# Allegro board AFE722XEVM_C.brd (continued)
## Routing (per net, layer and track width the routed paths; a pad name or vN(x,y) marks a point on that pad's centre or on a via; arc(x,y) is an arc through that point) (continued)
5V:
  vias: v1(123.83,103.12) v1(123.83,102.49) v1(123.83,101.85) v1(123.83,101.22) v1(123.83,100.58) v1(124.46,103.12) v1(124.46,102.49) v1(124.46,101.85) v1(124.46,101.22) v1(124.46,100.58) v1(124.46,99.95)
+1.8V_CLK: length 6.2
  TOP w0.254: U1.10 48.88,43.98 v1(49.45,44.55) 49.48,44.55 v1(49.91,44.98) ; C2.1 50.69,46.04 v1(50.42,45.77)
  BOTTOM w0.508: C4.1 49.25,44.2 49.25,44.3 49.91,44.96 v1(49.91,44.98) 50.42,45.49 v1(50.42,45.77) ; v1(50.06,48.44) 50.73,47.77 C3.1 v1(49.99,47.02)
  vias: v1(47.6,15.49) v1(47.6,14.86) v1(47.6,14.22) v1(48.23,15.49) v1(48.23,14.86) v1(48.23,14.22) v1(48.87,15.49) v1(48.87,14.86) v1(48.87,14.22)
+1.8VA_ADC: length 30.3
  TOP w0.254: C25.1 v1(53.29,43.03) ; 52.4,41.17 52.06,40.84 U1.1
  TOP w0.305: v1(54.1,39.95) 54.13,39.98 54.13,40.87 v1(53.87,41.12) 53.75,41 53.06,41 v1(52.96,40.89) 52.68,40.89 52.4,41.17 v1(52.73,41.5) ; v1(53.29,43.03) 52.96,43.03 v1(52.73,42.8) 52.5,43.03 v1(51.99,43.03) 51.64,42.67 v1(51.64,42.49) 51,41.86 51,41.85 ; v1(53.21,39.4) 53.21,38.96 v1(53.04,38.79) v1(52.6,39.22) 52.09,39.73 U1.64 ; v1(52.55,37.82) 52.55,37.87 v1(52.1,38.33) 51.4,39.02 U1.62 ; C23.1 v1(52.12,44.65) 51.64,44.65 v1(51.41,44.42) 51.41,44.17 51.13,43.89 v1(51.1,43.89) 50.9,43.89 v1(50.52,43.51) 49.94,42.93 U1.7
  BOTTOM w0.508: 52.31,39.89 52.31,39.69 52.6,39.4 v1(53.21,39.4) ; 52.26,41.03 v1(52.73,41.5) ; 52.26,41.03 C26.1 ; 52.26,41.03 52.82,41.03 v1(52.96,40.89) ; 54.76,40.61 54.36,40.61 v1(53.87,41.12) ; 54.76,40.61 C35.1 ; 54.76,40.61 v1(54.1,39.95) ; v1(53.04,38.79) 52.58,38.79 52.06,39.31 C28.1 ; v1(53.29,43.03) 52.96,43.03 v1(52.73,42.8) C32.1 ; 51.3,38.72 51.7,38.72 v1(52.1,38.33) 52.1,38.28 v1(52.55,37.82) ; v1(52.12,44.65) 51.64,44.65 v1(51.41,44.42) 51.41,44.17 50.8,43.56 50.14,43.56 C29.1 ; C31.1 50.52,42.82 v1(50.52,43.51) ; 50.96,42.15 51.3,42.15 v1(51.64,42.49) 51.99,42.85 v1(51.99,43.03)
  vias: v1(47.6,19.43) v1(47.6,18.8) v1(47.6,18.16) v1(48.23,19.43) v1(48.23,18.8) v1(48.23,18.16) v1(48.87,19.43) v1(48.87,18.8) v1(48.87,18.16)
+1.8VD: length 25
  TOP w0.254: v1(47.88,33.45) 47.88,33.55 47.4,34.03 47.19,34.03 46.8,34.43 U1.49 ; C8.1 38.37,42.15 v1(38.66,41.86) 38.63,41.83 v1(38.63,41.12) ; C10.1 41.47,35.04 41.68,35.26 v1(41.68,35.38) 41.74,35.38 42.24,35.88 42.24,35.91 v1(42.6,36.27) 43.22,36.9 U1.41 ; v1(39.78,41.4) 40.39,40.79 U1.32 ; v1(43.81,46.53) 43.97,46.38 44.25,46.38 44.6,46.03 44.6,45.87 44.99,45.48 U1.19 ; C6.1 v1(38.26,38.67) ; v1(41.83,44.27) 42.24,43.87 v1(42.29,43.87) 42.87,43.29 U1.25 ; v1(39.95,40.69) 39.57,40.69 v1(39.28,40.4)
  BOTTOM w0.381: 39.78,41.38 v1(39.78,41.4) ; C7.1 40.22,40.96 v1(39.95,40.69) 39.69,40.42 C19.1 v1(39.28,40.4)
  BOTTOM w0.508: v1(38.63,41.12) 38.63,41.83 v1(38.66,41.86) ; v1(38.63,41.12) 37.94,40.43 C11.1 37.94,40.34 v1(38.66,39.62) 38.66,39.07 v1(38.26,38.67) ; v1(38.63,41.12) 38.63,40.97 39.24,40.36 39.28,40.36 ; C5.1 42.63,43.47 v1(41.83,44.27) ; v1(39.28,40.4) 39.28,40.47 ; v1(44.07,45.85) 44.58,45.85 C13.1 ; v1(44.07,45.85) 44.07,45.21 C12.1 ; v1(44.07,45.85) 43.81,46.1 v1(43.81,46.53) ; v1(47.88,33.45) 47.12,33.45 v1(46.89,33.68) 46.89,34.27 C20.1 ; v1(41.68,35.38) 41.73,35.43 42.11,35.43 42.52,35.84 42.52,36.2 v1(42.6,36.27) C9.1
  vias: v1(42.37,20.22) v1(42.37,19.46) v1(42.37,18.69) v1(42.37,17.93) v1(42.37,17.17) v1(42.37,16.41) v1(42.37,15.65) v1(42.37,14.88) v1(42.37,14.12) v1(42.37,13.36) v1(43.13,19.96) v1(43.13,17.55) v1(43.13,16.03) v1(43.13,13.61) v1(43.51,16.79) v1(120.4,76.45) v1(120.4,75.82) v1(120.4,75.18) v1(120.4,74.55) v1(121.03,76.45) v1(121.03,75.82) v1(121.03,75.18) v1(121.03,74.55) v1(121.67,76.45) v1(121.67,75.82) v1(121.67,75.18) v1(121.67,74.55) v1(122.3,76.45) v1(122.3,75.82) v1(122.3,75.18) v1(122.3,74.55) v1(122.94,76.45) v1(122.94,75.82) v1(122.94,75.18) v1(122.94,74.55)
+3.3V_CLK: length 62.2
  TOP w0.254: v1(90.11,75.5) 90.46,75.86 C68.1 ; C86.1 93.13,58.94 v1(92.84,59.23) ; U2.11 87.62,62.11 87.22,61.72 87.22,61.35 86.68,60.81 v1(86.49,60.81) ; v1(78.87,67.64) 79.02,67.49 FB13.2 78.61,67.11 v1(78.49,67.23) ; v1(96.01,62.43) 96.3,62.14 C88.1 ; 87.62,70.26 87.62,70.27 v1(87.02,70.87) ; v1(89.74,72.39) 89.38,72.03 89.38,72.03 ; v1(88.04,71.96) 88.67,71.32 U2.51 ; U2.19 91.15,61.05 v1(91.77,60.43) ; v1(90.45,72.72) 90.6,72.57 90.6,72.19 90.44,72.03 ; v1(96.24,67.69) 95.99,67.69 95.39,67.1 U2.34 ; v1(92.86,61.47) 92.21,62.12 U2.22 ; v1(93.88,62.61) 93.3,63.19 U2.25 ; U2.5 85.49,64.21 v1(84.89,63.6) ; v1(85.57,62.26) 85.65,62.26 v1(86,62.61) 86.55,63.16 U2.8 ; v1(84.48,63.98) 85.1,64.6 U2.4 ; C63.1 88.9,75.31 v1(88.9,74.93) ; v1(93.93,69.88) 93.83,69.77 93.83,69.76 U2.40 ; C144.1 v1(94.92,61.29) ; U2.57 86.55,69.2 v1(85.9,69.85) ; U2.31 95.42,65.31 v1(95.99,64.74) ; C146.1 v1(93.85,60.3) ; U2.28 94.35,64.25 v1(94.91,63.69) ; C67.1 v1(81.83,67.88) ; 89.93,76.42 v1(89.64,76.12) ; v1(95.05,68.86) 94.33,68.15 U2.37 ; U2.60 85.45,68.14 84.99,68.61 v1(84.58,68.61) ; 92.21,70.26 92.21,70.29 v1(92.84,70.92) ; U2.14 88.68,61.07 v1(88.09,60.48) ; 96.15,70.12 v1(95.83,69.8) ; C62.1 v1(96.65,63.04)
  TOP w0.305: U2.63 83.85,67.67 v1(83.62,67.67)
  TOP w0.508: C179.1 v1(75.77,104.37) ; v1(88.09,56.95) 87.72,57.32 R148.1 ; R99.2 92.71,73.89 v1(92.33,73.51) ; R107.2 131.7,72.9 JP7.1 ; R98.2 94.12,72.45 v1(93.78,72.11) ; v1(81.69,70.71) 82.08,70.32 R85.2 ; v1(99.64,69.88) 99.16,69.39 R105.2 ; v1(90.91,74.96) 91.28,75.33 91.29,75.33 ; R166.1 v1(70.08,86.23) ; v1(85.12,59.92) 85.56,59.48 R149.1
  L3_PWR w1.016: 114.94,69.85 128.4,69.85 129.41,70.87 JP7.1
  BOTTOM w0.254: v1(83.9,63.65) 83.9,64.06 84.49,64.66 C78.1 ; v1(84.4,69.19) 84.86,69.19 85.56,68.49 C64.1 ; C80.1 88.48,60.19 v1(88.11,59.82) ; C59.1 91.91,60.92 92.35,60.48 v1(92.35,60.22) ; C82.1 87.41,62.07 86.82,61.47 v1(86.74,61.47) ; v1(83.24,67.18) 83.36,67.06 84.18,67.06 C76.1 ; v1(86,62.61) 86.4,63 C84.1
  BOTTOM w0.508: v1(89.56,75.01) 89.94,74.62 R101.2 89.94,74.45 v1(89.48,73.99) ; R106.2 100.47,68.75 v1(100.84,69.11) ; C77.1 97.43,64.29 ; 97.43,64.29 97.43,64.28 v1(96.8,63.65) ; 97.43,64.29 v1(96.88,64.85) ; R110.2 v1(92.1,55.35)
+3.3VA_DAC: length 25.1
  TOP w0.254: U1.14 47.47,45.41 47.96,45.9 47.96,46.1 v1(48.01,46.15) ; C14.1 45.33,49.42 44.84,48.93 v1(44.84,48.72) ; v1(48.11,46.96) 48.11,46.94 v1(48.54,46.51) ; C17.1 v1(44.42,47.98) ; v1(49.48,45.57) 49.1,45.19 v1(49.1,45.11) 49.1,44.99 48.53,44.42 48.53,44.39 ; v1(42.39,46.02) 42.39,46.1 C34.1 ; v1(45.57,46.81) 45.44,46.69 45.44,46.35 U1.17 45.74,46.09 v1(46.15,46.51) ; v1(42.77,45.39) v1(43.23,44.93) 43.93,44.34 U1.22 ; C22.1 v1(48.49,47.62)
  TOP w0.305: v1(49.1,45.11) 48.94,44.96 48.94,44.8 48.53,44.39 U1.11
  TOP w0.508: R53.1 v1(39.45,68.71) ; R12.1 v1(56.87,68.71) ; R54.1 v1(37.44,68.71) ; R13.1 v1(54.86,68.71)
  BOTTOM w0.508: v1(46.15,46.51) 45.85,46.81 v1(45.57,46.81) 45.4,46.65 C33.1 ; R50.2 v1(40.49,74.45) ; C15.1 47.15,46.01 v1(48.11,46.96) 48.49,47.35 v1(48.49,47.62) ; 46.06,48.72 C18.1 v1(46.12,47.51) ; 46.06,48.72 v1(44.84,48.72) ; 46.06,48.72 v1(45.39,48.06) 45.31,47.98 v1(44.42,47.98) ; v1(42.39,46.02) 42.77,45.64 v1(42.77,45.39) v1(43.23,44.93) ; v1(48.54,46.51) 48.18,46.15 v1(48.01,46.15) 48.01,46.1 47.71,45.81 C21.1 ; v1(49.48,45.57) 49.48,45.54 49.1,45.16 v1(49.1,45.11) 49.05,45.11 C16.1 ; R48.2 v1(57.96,74.65)
  vias: v1(114.94,84.45) v1(114.94,83.82) v1(114.94,83.19) v1(115.57,84.45) v1(115.57,83.82) v1(115.57,83.19) v1(116.2,84.45) v1(116.2,83.82) v1(116.2,83.19) v1(116.84,84.45) v1(116.84,83.82) v1(116.84,83.19) v1(117.48,85.73) v1(117.48,85.09) v1(117.48,84.45) v1(117.48,83.82) v1(117.48,83.19) v1(117.86,87.88) v1(118.11,85.73) v1(118.11,85.09) v1(118.11,84.45) v1(118.11,83.82) v1(118.11,83.19)
+5VA: length 6.8
  TOP w0.508: 51.69,59.79 v1(52.15,59.79) ; R132.1 v1(48.18,59.79) ; R118.1 v1(46.18,59.77) ; R113.1 v1(42.16,59.77)
  BOTTOM w0.508: v1(39.45,104.6) 39.98,104.6 40.39,104.19 FB5.1 40.39,103.94 39.98,103.53 v1(39.45,103.53) ; v1(39.57,88.14) 40.06,88.14 40.51,88.6 40.51,88.87 40.16,89.23 v1(39.6,89.23)
+6.0VDC: length 4.3
  TOP w0.508: v1(116.97,106.05) 116.84,106.05 116.08,105.28 ; 116.08,105.28 v1(116.97,104.39) ; 116.08,105.28 C125.1 ; v1(118.87,106.05) 118.97,105.94 C186.1 118.97,104.5 v1(118.87,104.39)
  vias: v1(109.47,110.49) v1(109.47,109.86) v1(109.47,109.22) v1(110.11,110.49) v1(110.11,109.86) v1(110.11,109.22) v1(110.74,110.49) v1(110.74,109.86) v1(110.74,109.22) v1(111.38,110.49) v1(111.38,109.86) v1(111.38,109.22) v1(117.6,106.05) v1(117.6,104.39) v1(118.24,106.05) v1(118.24,104.39) v1(119.51,106.05) v1(119.51,104.39)
GND: length 316.8
  TOP w0.254: 86.2,68.85 86.2,68.84 v1(87.07,67.97) ; C62.2 v1(97.66,62.03) ; U6.2 131.6,92 v1(131.62,92.02) ; C14.2 44.31,49.85 v1(43.94,49.48) ; v1(51.41,46.76) 51.14,46.49 51.14,46.47 ; C66.2 v1(90.65,77.14) ; C25.2 v1(54.64,43.03) ; U2.61 85.14,67.77 v1(85.98,66.93) ; v1(94.89,59.23) 94.6,59.53 C146.2 ; v2(89.91,62.6) 89.91,62.2 ; C69.2 96.58,70.57 v1(96.9,70.89) ; U8.4 131.06,81.17 v1(131.37,81.48) ; C86.2 v1(93.9,58.19) ; v2(93.51,66.2) 95.07,66.2 95.29,65.98 95.43,65.98 U2.32 ; v1(129.67,80.26) 129.97,80.57 U8.1 ; C144.2 v1(95.97,60.24) ; 90.92,76.29 v1(91.24,76.61) ; v1(131.62,92.58) 131.69,92.65 U6.6 ; C8.2 v1(37.59,42.88) ; C10.2 v1(40.74,34.29) ; U2.2 84.43,65.33 84.89,65.79 v1(85.65,65.79) ; C17.2 v1(43.33,49.07) ; C65.1 v1(79.68,67.74) ; C6.2 v1(36.93,38.63) ; C23.2 v1(53.54,44.65) ; C88.2 v1(97.03,61.39) ; C34.2 v1(41.38,47.12) ; C67.2 v1(80.77,68.94) ; 80.51,68.06 v1(80.21,68.35) ; C22.2 v1(48.49,49.17)
  TOP w0.305: J14.61 v1(75.35,2.19) ; J14.59 v1(80.84,2.23) ; v2(44.43,38.46) 44.43,38.05 44.13,37.74 v1(44.07,37.74) ; v1(72.34,10.69) 72.34,10.69 J14.74 v1(72.34,8.3) ; v2(48.92,41.16) 49.45,41.69 v1(49.45,41.71) ; 49.97,40.11 v2(49.82,40.26) 49.96,40.26 50.34,40.64 50.42,40.72 v1(50.42,40.74) ; 49.97,40.11 50.34,39.74 v1(50.34,39.7) ; 49.97,40.11 50.1,40.23 50.62,40.23 v1(50.75,40.11) ; J14.91 v1(67.84,2.18) ; J14.17 v1(91.35,2.14) ; J14.97 v1(66.34,2.2) ; J14.67 v1(73.85,2.17) ; C85.1 v1(84.3,72.34) ; v1(45.77,44.48) 46.23,44.02 v2(46.23,43.85) 46.28,43.9 46.28,44.38 ; v1(82.3,10.49) 82.34,10.45 J14.54 v1(82.34,8.32) ; v2(47.13,42.95) 47.13,43.16 47.55,43.59 v1(47.55,43.61) ; v2(47.13,41.16) 47.14,41.17 47.14,42.14 48.08,43.08 v1(48.11,43.08) ; J14.29 v1(88.34,2.19) ; J14.12 v1(92.85,10.61) ; v1(49.96,41.2) 49.89,41.2 48.89,40.21 48.89,39.39 v2(48.92,39.36) ; J14.30 v1(88.34,10.56) ; v1(73.84,10.69) 73.85,10.69 J14.68 v1(73.85,8.34) ; J14.24 v1(89.84,10.61) ; v2(42.64,40.26) 42.14,40.26 v1(41.83,40.56) ; J14.6 v1(94.35,10.62) ; J14.85 v1(69.34,2.21) ; v2(46.23,42.06) 46.28,42.11 46.28,42.98 45.29,43.97 v1(45.26,43.97) ; v2(48.02,42.06) 48.17,41.91 48.46,41.91 v1(48.84,42.29) ; J14.104 v1(64.84,10.5) ; J14.60 v1(80.84,8.35) ; J14.79 v1(70.84,2.19) ; v1(83.85,10.52) 83.84,10.51 J14.48 v1(83.84,8.33) ; J14.35 v1(86.84,2.18) ; v1(46.76,44.42) 46.76,44.38 46.28,44.38 ; J14.73 v1(72.34,2.18) ; J14.11 v1(92.85,2.14) ; 46.28,44.38 v1(46.28,44.83) ; J14.53 v1(82.34,2.2) ; v1(85.47,10.67) 85.34,10.54 J14.42 v1(85.34,8.38) ; J14.80 v1(70.84,10.59) ; J14.36 v1(86.84,10.54) ; v2(46.23,36.67) 46.2,36.64 v1(46.2,35.69) ; J14.86 v1(69.34,10.54) ; v1(43.59,42.29) 44.81,41.07 45.24,41.07 v2(45.33,41.16) ; D1.2 v1(93.73,81) ; D1.2 v1(91.92,81) ; D1.2 v1(92.86,81.94) ; J14.5 v1(94.35,2.2) ; J14.92 v1(67.84,10.54) ; J14.18 v1(91.35,10.62) ; 88.4,75.81 v1(88.09,76.12) ; J14.23 v1(89.84,2.13) ; J14.110 v1(63.34,10.5) ; J14.98 v1(66.34,10.51) ; J14.103 v1(64.84,2.25) ; J14.62 v1(75.35,8.32) ; J14.116 v1(61.84,10.53) ; J14.109 v1(63.34,2.23) ; J14.47 v1(83.84,2.2) ; J14.41 v1(85.34,2.19)
  TOP w0.381: v1(86.08,65.35) 86.08,65.38 87.02,66.32 87.99,66.32 v2(88.12,66.2) ; v1(87.07,67.97) 87.95,67.09 v2(89.02,67.09) ; v1(87.38,64.08) 87.38,64.09 87.68,64.4 v2(88.12,64.4) ; v1(90.3,61.9) 90.22,61.9 89.91,62.2 89.66,62.2 v1(89.46,62) ; v2(86.32,66.2) 86.32,66.59 v1(85.98,66.93) ; v2(86.32,66.2) 86.25,66.27 85.62,66.27 v1(85.47,66.42) ; v2(86.32,66.2) 86.03,66.2 85.65,65.81 v1(85.65,65.79) ; v2(87.22,67.09) 86.87,67.09 86.56,67.4 v1(86.56,67.49) ; v1(88.4,63.03) 88.88,63.5 v2(89.02,63.5)
  TOP w0.406: J1.2 v1(139.32,39.01) v1(138.43,39.01) ; v2(91.71,67.99) v2(90.81,67.09) v2(89.91,66.2) ; v1(138.43,59.33) v1(139.32,59.33) J3.2 ; v1(138.43,53.75) v1(139.32,53.75) J3.3 ; v1(138.43,43.59) v1(139.32,43.59) J4.3 ; v2(91.71,64.4) v2(90.81,65.3) v2(89.91,66.2) ; v2(89.91,66.2) v2(89.91,67.99) v2(89.91,69.79) ; v2(89.91,66.2) v2(89.02,65.3) v2(88.12,64.4) ; v2(89.91,66.2) v2(89.02,67.09) ; v2(48.02,38.46) v2(47.13,39.36) v2(46.23,40.26) ; v1(140.21,49.17) v1(139.32,49.17) v1(138.43,49.17) ; v1(131.62,91.47) U6.7 ; v1(138.43,33.43) v1(139.32,33.43) J1.3
  TOP w0.508: v1(77.04,59.84) 76.28,59.08 76.28,59.06 ; v1(98.68,68.05) 98.24,68.48 R108.1 ; v1(19.63,31.2) 19.63,32.33 19.68,32.38 ; 83.69,33.15 v1(84.2,33.15) ; C132.2 v1(127.51,87.2) ; v1(42.32,97.94) C96.1 v1(42.8,98.45) 42.8,98.96 ; v1(118.36,112.14) D2.2 119.38,111.12 ; R89.2 v1(87.05,86.63) ; v1(40.54,51.33) 40.93,50.94 R52.2 ; C109.1 v1(52.72,97.9) ; U17.4 v1(68.06,91.96) ; U17.4 v1(68.06,94.14) ; U17.4 v1(66.78,93.07) ; R116.2 v1(41.91,63.83) ; v1(53.34,78.64) T5.3 v1(52.41,77.44) ; C130.2 v1(133.76,93.45) ; 76.28,56.36 76.28,56.34 v1(77.01,55.6) ; v1(93.85,75.03) 93.45,74.63 R103.1 ; R97.2 84.09,59.5 v1(83.69,59.11) ; T6.1 19.68,32.38 ; 19.68,32.38 v1(18.73,32.38) ; v1(92.43,76.5) 92.01,76.08 R104.1 ; C49.1 v1(94.23,85.14) ; v1(39.09,49.86) 39.46,49.49 R63.2 ; C181.2 v1(82.96,100.69) ; C181.2 v1(81.93,101.71) ; C181.2 v1(81.93,99.71) ; v1(87.4,56.21) 87.01,56.6 87,56.6 ; v1(43.28,94.89) C95.1 v1(42.8,94.36) v1(42.8,93.32) ; R39.1 v1(102.62,46) R37.2 ; C137.2 132,81.94 v1(131.9,81.84) ; C178.2 v1(78.36,97.89) ; L8.2 v1(71.88,60.5) ; v1(42.8,99.52) 42.8,98.96 ; 42.8,98.96 42.32,98.96 v1(42.29,98.98) ; C72.1 79.79,62.38 v1(79.38,62.79) ; v1(45.06,13.59) FB11.2 v1(45.06,16.18) ; C73.1 v1(70.51,60.78) ; R24.2 v1(102.49,30.35) R26.1 ; v1(45.06,17.53) FB17.2 v1(45.06,20.09) ; VCXO1.3 v1(86.78,101.69) ; VCXO1.3 v1(87.86,98.83) ; VCXO1.3 v1(87.86,104.55) ; v1(130.43,83.31) 130.17,83.57 C138.2 ; C43.1 v1(84.2,43.31) ; v1(76.1,60.71) 75.38,59.99 FLT1.3 ; v1(34.98,77.26) T7.3 v1(35.92,78.43) ; C125.2 113.13,105.05 v1(113.13,104.14) ; C125.2 113.13,105.51 v1(113.13,106.43) ; C125.2 v1(112.01,105.28) ; v1(16.66,33.66) 16.66,34.17 C60.1 ; C182.2 v1(78.33,98.91) ; C52.1 v1(92.84,85.67) ; R83.2 v1(91.05,86.63) ; C1.2 v1(55.3,36.14) ; R129.2 v1(52.43,63.86) ; C186.2 v1(121.16,105.28) ; FLT1.4 v1(72.97,59.66) ; v1(81.58,61.29) 81.94,61.65 81.94,61.66 ; FLT1.7 74.48,55.44 v1(74.9,55.02) ; R77.2 62.63,61.33 v1(62.26,60.96) ; R164.1 v1(67.46,104.37) ; R167.1 v1(70.05,85.22) ; v1(84.45,58.37) 84.84,58.76 R151.2 ; C108.1 v1(52.77,94.85) ; R86.2 v1(66.67,55.83) ; C48.1 v1(96.52,87.15) ; L9.2 78.5,62.04 v1(78,62.53) ; R122.2 v1(46.43,63.83) ; R135.2 v1(47.9,63.86) ; R90.1 v1(84.61,70.71) ; 73.58,56.36 v1(72.82,55.6) ; C180.2 v1(78.38,104.95) ; R123.1 v1(46,90.43) ; R31.2 v1(114.05,26.24) ; C179.2 v1(77.37,105) ; R45.2 v1(113.92,42.01) ; R124.2 v1(49.31,92.5) ; R102.1 v1(95.25,73.53)
  TOP w0.762: v1(131.06,87.25) 131.01,87.3 C133.2
  BOTTOM w0.254: C76.2 85.15,66.74 v1(85.47,66.42) ; C80.2 88.91,61.46 v1(89.46,62) ; C59.2 v1(90.3,61.9) ; C84.2 v1(87.38,64.08) ; v1(86.08,65.35) 85.81,65.09 C78.2 ; 87.87,62.5 v1(88.4,63.03) ; v1(86.56,67.49) 86.02,68.03 C64.2
  BOTTOM w0.305: v1(123.28,5.73) U4.25 v1(120.49,5.73) ; v1(123.31,5.08) U4.26 v1(120.48,5.08) ; v1(120.48,8.33) U4.21 123.37,8.33 v1(123.44,8.26) ; 51.01,40.37 v1(50.75,40.11) 51.12,39.74 C28.2 ; v1(120.53,10.2) 120.61,10.28 U4.18 123.25,10.28 v1(123.33,10.2) ; v1(113.66,7.68) U4.7 v1(116.46,7.68)
  BOTTOM w0.381: v1(43.59,42.29) 43.07,42.81 C5.2 ; v1(46.2,35.69) 46.47,35.42 C20.2 ; C31.2 49.97,42.23 v1(49.45,41.71) ; C24.2 50.48,41.72 v1(49.96,41.2) ; v1(41.83,40.56) 41.8,40.53 C7.2 ; C26.2 51.24,40.6 51.01,40.37 ; 51.09,41.16 51.07,41.16 50.65,40.74 v1(50.42,40.74) ; v1(44.07,37.74) C9.2 ; v1(48.11,43.08) 48.63,43.6 C4.2 ; C29.2 v1(48.84,42.29) ; v1(45.26,43.97) 44.72,44.51 C12.2 ; v1(47.55,43.61) C16.2 ; C21.2 v1(46.76,44.42) ; v1(53.21,40.26) 53.19,40.23 52.83,40.23 C30.2 ; C13.2 45.28,44.97 v1(45.77,44.48) ; C33.2 45.83,45.28 v1(46.28,44.83) 46.72,45.28 C15.2 ; 40.12,39.97 39.85,39.7 v1(39.5,39.7) ; v1(50.34,39.7) 50.86,39.18 C27.2
  BOTTOM w0.406: J16.6 v1(139.87,12.25) ; J16.7 v1(134.37,12.25) ; U7.6 v1(130.96,95.15) v1(130.2,95.15) v1(129.44,95.15) ; v1(131.95,84.07) v1(131.95,83.31) U9.6 v1(131.95,82.55) ; J16.5 v1(135.86,13.67)
  BOTTOM w0.508: C81.2 v1(36.42,74.45) ; R119.1 v1(122.4,95.73) ; FB12.2 v1(123.65,81.1) ; v1(74.12,93.8) U16.4 v1(73.46,92.89) ; C136.2 v1(127.51,86.23) ; v1(131.83,93.73) v1(131.72,94.39) 131.83,94.97 131.72,95.07 v1(131.72,95.15) ; 56.66,38.16 56.09,38.16 v1(56.01,38.07) ; 56.66,38.16 v1(57.07,37.74) ; 56.66,38.16 C35.2 ; v1(98.4,62.03) 98.91,62.54 ; 98.91,62.54 99.21,62.54 v1(99.47,62.28) ; 98.91,62.54 C77.2 ; C150.2 v1(118.82,77.04) ; C121.2 v1(121.01,113.13) ; C121.2 v1(119.55,112.1) ; C121.2 v1(122.52,112.1) ; C148.2 v1(117.3,80.72) ; v1(122.81,103.5) C187.2 v1(121.79,104.27) ; v1(43.56,51.31) 44.3,50.56 C18.2 ; v1(39.7,101.78) C105.2 v1(40.75,100.83) ; C18.2 44.3,49.84 v1(43.94,49.48) ; C18.2 43.6,50.54 v1(43.28,50.22) ; v1(96.72,43.89) 96.8,43.97 C46.1 ; FB9.2 v1(121.29,90.81) ; v1(118.62,110.62) 118.59,110.59 C122.2 ; v1(115.95,88.01) FB15.2 v1(115.95,85.47) ; C89.2 92.47,56.47 v1(92.86,56.08) ; C119.2 v1(129.9,13.87) ; v1(131.72,95.15) v1(132.49,94.39) v1(132.59,93.73) ; v1(131.72,95.15) U7.6 ; C128.2 v1(124.46,98.93) ; C56.2 v1(61.93,52.55) ; J16.8 v1(134.37,21.05) ; C141.2 v1(127.89,75.21) ; C117.2 v1(125.86,13.54) ; v1(39.8,91.69) C97.2 v1(39.83,90.58) ; C123.2 v1(113.03,112.52) ; C79.2 v1(53.85,74.65) ; J16.9 v1(139.87,21.01) ; C139.2 v1(118.82,78.05) ; C40.1 v1(96.62,28.14) ; C143.2 v1(115.44,90.68) ; C131.2 v1(114.81,92.2) ; v1(36.83,42.93) 36.14,42.23 36.13,42.23 ; C149.2 v1(117.93,79.2) ; C118.2 v1(129.84,9.5) ; C120.2 v1(122.71,14.73) ; R5.2 v1(53.57,35.18) ; C147.2 v1(116.33,88.52) ; C124.2 v1(111.89,112.01) ; 36.13,42.23 v1(35.36,43) ; 36.13,42.23 C11.2 ; U18.2 v1(124.46,105.66) ; v1(53.29,50.27) 52.57,49.55 C3.2 52.53,49.55 v1(51.84,50.24) ; R14.1 v1(41.1,50.01) ; C115.2 v1(127.51,11.94) ; v1(42.29,100) 42.8,100 v1(42.8,99.52) 42.82,99.49 C102.2 v1(42.29,98.98) ; v1(103,68.12) 102.54,67.66 C75.2 ; C135.2 v1(126.49,87.76) ; C45.1 v1(108.2,43.99) ; C116.2 v1(129.92,5.82) ; C53.2 v1(96.62,93.42) ; C39.1 v1(108.33,28.32) ; C145.2 v1(116.33,89.53) ; C50.2 v1(97.46,94.95) ; v1(42.29,92.84) 42.8,92.84 v1(42.8,93.32) v1(42.8,94.36)
  BOTTOM w0.762: C142.2 v1(128.27,74.17) ; U7.3 131.01,87.3 v1(131.06,87.25) 130.94,87.12 C151.2 v1(130.94,85.47) ; C140.2 131.8,75.16 v1(131.95,75.31) U9.3
  BOTTOM w1.016: U14.3 v1(113.13,101.85)
  vias: v1(0.66,97.43) v1(0.64,95.25) v1(0.64,92.71) v1(0.64,90.17) v1(0.64,87.63) v1(0.64,85.09) v1(0.64,82.55) v1(0.64,80.01) v1(0.64,77.47) v1(0.64,74.93) v1(0.64,72.39) v1(0.64,69.85) v1(0.64,67.31) v1(0.64,64.77) v1(0.64,62.23) v1(0.64,59.69) v1(0.64,57.15) v1(0.64,54.61) v1(0.64,52.07) v1(0.64,49.53) v1(0.64,46.99) v1(0.64,44.45) v1(0.64,41.91) v1(0.64,39.37) v1(0.64,36.83) v1(0.64,34.29) v1(0.64,31.75) v1(0.64,29.21) v1(0.64,26.67) v1(0.64,24.13) v1(0.64,21.59) v1(0.69,18.39) v1(0.64,15.88) v1(1.27,99.31) v1(2.03,14.48) v1(3.18,100.97) v1(3.81,12.38) v1(5.08,101.92) v1(6.43,55.78) v1(6.35,51.77) v1(6.35,48.26) v1(6.35,45.72) v1(6.35,12.38) v1(6.48,63.7) v1(6.53,53.82) v1(6.63,58.83) v1(6.55,29.92) v1(6.65,49.76) v1(6.68,32.36) v1(6.91,60.3) v1(7.09,61.87) v1(7.62,101.92) v1(7.75,63.86) v1(8.23,86.54) v1(8.23,78.33) v1(8.23,75.13) v1(8.23,69.67) v1(8.23,67.82) v1(8.23,66.55) v1(8.23,64.69) v1(8.23,56.03) v1(8.23,52.96) v1(8.23,49.38) v1(8.23,47.75) v1(8.23,42.37) v1(8.23,41.38) v1(8.23,39.34) v1(8.23,38.35) v1(8.23,33.07) v1(8.23,29.67) v1(8.2,27.74) v1(8.25,85.6) v1(8.25,84.66) v1(8.25,82.37) v1(8.25,81.48) v1(8.25,80.33) v1(8.25,79.32) v1(8.25,76.05) v1(8.25,73.96) v1(8.25,73.05) v1(8.25,71.96) v1(8.25,68.78) v1(8.25,65.6) v1(8.25,61.87) v1(8.25,60.33) v1(8.25,59.33) v1(8.25,58.32) v1(8.25,55.04) v1(8.25,53.98) v1(8.25,51.99) v1(8.25,48.7) v1(8.25,46.51) v1(8.25,45.59) v1(8.25,44.65) v1(8.25,40.32) v1(8.25,36.02) v1(8.25,35.03) v1(8.25,33.97) v1(8.25,32) v1(8.25,28.7) v1(8.94,32.16) v1(8.97,28.7) v1(9.19,55.27) v1(9.19,53.09) v1(9.27,47.4) v1(9.42,63.86) v1(9.42,59.92) v1(9.73,61.9) v1(9.91,58.01) v1(9.98,31.09) v1(10.16,101.92) v1(10.16,68.58) v1(10.21,27.46) v1(10.16,12.38) v1(10.97,46.48) v1(12.01,27.46) v1(12.07,87.25) v1(12.7,101.92) v1(12.7,79.88) v1(12.7,72.39) v1(12.7,61.87) v1(12.73,59.87) v1(12.67,57.96) v1(12.73,55.5) v1(12.67,52.4) v1(12.7,29.87) v1(12.7,12.38) v1(12.9,63.86) v1(12.95,49.86) v1(13.23,46.53) v1(13.61,36.14) v1(13.92,27.46) v1(14.1,42.39) v1(14.12,30.68) v1(14.43,52.35) v1(14.48,90.55) v1(14.5,55.52) v1(14.61,61.87) v1(14.73,26.75) v1(14.86,76.07) v1(14.86,57.99) v1(14.99,83.57) v1(14.96,46.53) v1(15.24,101.92) v1(15.24,68.58) v1(15.27,59.89) v1(15.24,12.38) v1(15.34,23.14) v1(15.52,30.43) v1(15.57,63.88) v1(15.54,49.86) v1(16.36,26.67) v1(16.51,58.67) v1(16.48,55.52) v1(16.43,52.32) v1(16.61,53.62) v1(16.89,93.34) v1(16.92,57.96) v1(16.84,46.56) v1(17.04,30.63) v1(17.14,87.25) v1(17.3,61.39) v1(17.78,101.92) v1(17.78,79.88) v1(17.78,72.39) v1(17.78,12.38) v1(17.91,26.67) v1(18.01,36.14) v1(18.08,63.91) v1(18.03,42.24) v1(18.06,38.58) v1(18.14,57.12) v1(18.31,51.89) v1(18.82,46.56) v1(18.77,41.15) v1(18.77,39.62) v1(18.77,34.32) v1(18.9,42.7) v1(18.85,30.63) v1(19,49.86) v1(19.3,55.09) v1(19.51,59.18) v1(19.56,90.55) v1(19.58,62.61) v1(19.53,26.77) v1(19.81,45.57) v1(19.89,43.21) v1(19.94,76.07) v1(20.07,83.57) v1(20.32,101.92) v1(20.32,12.38) v1(20.35,49.86) v1(20.57,30.51) v1(20.73,57.02) v1(20.73,44.6) v1(20.8,34.29) v1(20.85,53.49) v1(20.95,61.24) v1(21.01,39.85) v1(21.29,26.75) v1(21.44,46.84) v1(22.23,87.25) v1(22.23,30.63) v1(22.3,59.59) v1(22.3,39.73) v1(22.4,55.4) v1(22.48,51.89) v1(22.45,45.87) v1(22.86,79.88) v1(22.86,72.39) v1(22.86,64.77) v1(22.91,26.67) v1(23.19,47.4) v1(23.39,44.65) v1(23.52,39.62) v1(23.44,29.87) v1(23.55,58.62) v1(23.77,44.32) v1(24.13,101.92) v1(24.13,53.62) v1(24.13,12.38) v1(24.49,27.46) v1(24.92,35.13) v1(25.02,76.07) v1(24.97,57.25) v1(24.94,30.38) v1(25.15,83.57) v1(25.4,89.92) v1(25.5,45.06) v1(25.53,41.94) v1(25.48,40.72) v1(25.48,39.6) v1(25.7,51.97) v1(25.88,27.81) v1(26.16,44.37) v1(26.24,23.16) v1(26.34,55.85) v1(26.39,38.02) v1(26.67,101.92) v1(26.67,64.77) v1(26.64,32.03) v1(26.7,28.68) v1(26.67,12.38) v1(27.05,51.89) v1(27.2,40.39) v1(27.3,113.03) v1(27.3,110.49) v1(27.3,107.95) v1(27.3,105.41) v1(27.3,102.87) v1(27.3,100.33) v1(27.3,97.79) v1(27.3,43.33) v1(27.3,16.51) v1(27.3,13.97) v1(27.3,11.43) v1(27.3,8.89) v1(27.3,6.35) v1(27.3,3.81) v1(27.36,54.43) v1(27.43,47.85) v1(27.56,27.86) v1(27.99,92.63) v1(28.02,89.84) v1(27.99,85.62) v1(28.02,83.74) v1(27.94,72.39) v1(27.94,60.96) v1(28.02,33.43) v1(27.94,0.64) v1(28.04,87.93) v1(28.07,81.15) v1(28.07,78.74) v1(28.07,76.45) v1(28.4,30.33) v1(28.63,46.79) v1(28.68,42.06) v1(28.75,53.42) v1(28.91,94.36) v1(28.96,26.42) v1(29.26,49.43) v1(29.26,38.28) v1(29.31,29.39) v1(29.34,75.23) v1(29.54,31.47) v1(29.74,45.62) v1(29.84,113.67) v1(30.02,95.53) v1(30.2,33.93) v1(30.25,51.92) v1(30.28,43.18) v1(30.35,89.66) v1(30.35,84.63) v1(30.35,77.72) v1(30.48,79.63) v1(30.48,60.96) v1(30.48,20.32) v1(30.48,12.7) v1(30.56,28.09) v1(30.68,48.01) v1(30.71,36.86) v1(30.81,73.76) v1(30.81,39.67) v1(30.99,31.47) v1(31.12,101.6) v1(31.12,0.64) v1(31.32,42.16) v1(31.55,76.35) v1(31.75,107.31) v1(31.75,69.85) v1(31.75,64.77) v1(31.75,57.15) v1(31.83,43.21) v1(32.03,46.66) v1(32.05,35.53) v1(32.16,95.81) v1(32.16,93.45) v1(32.26,51.89) v1(32.31,33.93) v1(32.38,72.26) v1(32.49,86.13) v1(32.49,38.07) v1(32.79,49.43) v1(32.84,75.03) v1(33.02,113.67) v1(33.02,16.51) v1(33.02,8.89) v1(33.3,41.86) v1(33.27,31.5) v1(33.4,89.28) v1(33.53,79.38) v1(33.63,34.44) v1(33.66,99.06) v1(33.96,48.23) v1(33.99,36.6) v1(34.11,43.23) v1(34.16,73.79) v1(34.29,110.49) v1(34.29,104.78) v1(34.26,70.48) v1(34.29,54.61) v1(34.29,0.64) v1(34.52,49.68) v1(34.49,40.69) v1(34.77,69.01) v1(34.77,67.49) v1(34.8,65.84) v1(34.75,64.01) v1(34.77,62.33) v1(34.77,60.53) v1(34.85,85.95) v1(35.03,53.7) v1(35.15,35.81) v1(35.18,33.88) v1(35.31,90.17) v1(35.26,48.01) v1(35.56,113.67) v1(35.56,73.91) v1(35.56,31.47) v1(35.69,39.42) v1(35.81,58.8) v1(36.07,94.62) v1(36.07,75.44) v1(36.5,55.17) v1(36.83,107.31) v1(36.83,101.6) v1(36.83,57.73) v1(36.78,51.94) v1(36.83,20.32) v1(36.83,12.7) v1(36.83,5.08) v1(36.83,0.64) v1(37.11,69.98) v1(37.11,67.82) v1(37.11,66.04) v1(37.11,64.39) v1(37.08,62.74) v1(37.13,60.78) v1(37.41,33.86) v1(37.67,86.41) v1(37.72,84.33) v1(37.69,80.92) v1(37.77,31.47) v1(37.85,78.99) v1(37.97,90.17) v1(37.97,56.59) v1(38.1,113.67) v1(38.1,104.78) v1(38.1,50.8) v1(38.15,53.31) v1(38.46,59.41) v1(38.91,54.05) v1(39.37,110.49) v1(39.37,99.06) v1(39.34,52.4) v1(39.37,24.13) v1(39.37,16.51) v1(39.37,0.64) v1(39.45,32.46) v1(39.62,93.98) v1(39.65,92.79) v1(39.67,54.84) v1(39.78,96.14) v1(39.8,69.98) v1(39.83,62.28) v1(39.85,67.74) v1(39.85,66.14) v1(39.85,64.31) v1(39.85,60.58) v1(39.85,58.85) v1(40.08,87.02) v1(40.08,84.61) v1(40.08,82.19) v1(40.06,80.14) v1(40.59,33.53) v1(40.59,31.75) v1(40.64,113.67) v1(40.64,8.89) v1(40.89,99.7) v1(40.92,54.81) v1(41,97.36) v1(41.25,78.92) v1(41.53,74.42) v1(41.45,29.79) v1(41.78,105.54) v1(41.91,108.33) v1(41.86,61.32) v1(41.91,0.64) v1(42.01,95) v1(42.04,93.75) v1(42.11,89.66) v1(42.11,67.67) v1(42.04,54.81) v1(42.14,69.8) v1(42.24,58.85) v1(42.8,113.67) v1(42.8,87.12) v1(42.82,82.75) v1(42.8,81.03) v1(42.8,70.61) v1(42.8,68.45) v1(42.85,85.06) v1(42.85,79.58) v1(42.85,78.16) v1(42.93,28.42) v1(43.21,73.63) v1(43.21,54.89) v1(43.21,53.62) v1(43.28,77.17) v1(43.23,75.44) v1(43.26,71.68) v1(43.38,52.32) v1(43.81,113.03) v1(43.81,111.76) v1(43.81,110.49) v1(43.81,109.22) v1(44.09,33.05) v1(44.35,26.95) v1(44.48,22.89) v1(44.45,5.08) v1(44.45,0.64) v1(44.55,97.71) v1(44.96,99.95) v1(45.11,91.41) v1(45.06,90.25) v1(45.21,94.11) v1(45.14,92.76) v1(45.31,98.2) v1(45.31,89.2) v1(45.26,68.25) v1(45.34,87.63) v1(45.34,84.71) v1(45.34,81.79) v1(45.34,78.99) v1(45.34,76.07) v1(45.34,73.53) v1(45.34,70.87) v1(45.59,54.74) v1(45.67,53.57) v1(45.64,33.53) v1(45.77,25.6) v1(46.1,108.33) v1(46.1,106.05) v1(46.1,103.89) v1(46.1,101.98) v1(46.13,99.72) v1(46.08,58.65) v1(46.3,67.84) v1(46.53,52.3) v1(46.53,50.27) v1(46.66,89.15) v1(46.77,97.16) v1(46.77,96.66) v1(46.77,96.15) v1(46.77,95.64) v1(46.84,55.63) v1(46.99,59.69) v1(46.99,11.43) v1(46.99,0.64) v1(47.12,66.93) v1(47.12,64.77) v1(47.12,61.85) v1(47.12,60.71) v1(47.17,24.18) v1(47.27,97.16) v1(47.27,96.66) v1(47.27,96.15) v1(47.27,95.64) v1(47.47,56.21) v1(47.78,97.16) v1(47.78,96.66) v1(47.78,96.15) v1(47.78,95.64) v1(47.8,55.17) v1(47.88,67.64) v1(48.03,89.2) v1(48.08,51.46) v1(48.16,58.65) v1(48.29,97.16) v1(48.29,96.66) v1(48.29,96.15) v1(48.29,95.64) v1(48.26,32.64) v1(48.39,50.42) v1(48.46,108.15) v1(48.46,105.99) v1(48.46,103.96) v1(48.46,101.68) v1(48.46,99.59) v1(48.44,22.91) v1(48.92,88.72) v1(48.89,79.25) v1(48.89,71.78) v1(48.95,93.27) v1(48.95,86.56) v1(48.95,84.53) v1(48.95,81.81) v1(48.95,76.78) v1(48.95,74.24) v1(48.95,69.93) v1(48.95,68.3) v1(49.1,53.77) v1(49.12,52.71) v1(49.17,54.89) v1(49.5,93.95) v1(49.53,8.89) v1(49.53,5.08) v1(49.71,98.65) v1(49.91,21.39) v1(50.16,0.64) v1(50.42,91.82) v1(50.5,94.97) v1(50.52,49.66) v1(50.55,113.03) v1(50.55,111.76) v1(50.55,110.49) v1(50.55,109.22) v1(50.62,50.75) v1(50.67,93.09) v1(50.88,97.97) v1(51.03,89.1) v1(51.05,87.71) v1(51.05,85.17) v1(51.05,82.63) v1(51.05,80.09) v1(51.05,77.55) v1(51.05,75.01) v1(51.05,72.47) v1(51.18,113.69) v1(51.21,20.17) v1(51.41,70.82) v1(51.41,69.62) v1(51.38,68.3) v1(51.61,53.42) v1(51.61,52.02) v1(51.64,54.81) v1(51.82,101.6) v1(52.07,104.78) v1(52.07,11.43) v1(52.17,69.24) v1(52.22,67.49) v1(52.22,56.72) v1(52.15,47.98) v1(52.37,18.92) v1(52.53,61.39) v1(52.65,90.88) v1(52.81,93.45) v1(52.76,49.23) v1(53.01,86.41) v1(52.98,84.02) v1(53.01,80.11) v1(53.01,75.74) v1(53.01,74.02) v1(53.01,45.36) v1(53.09,88.65) v1(53.04,82.12) v1(53.11,54.81) v1(53.34,113.67) v1(53.34,107.95) v1(53.34,0.64) v1(53.44,99.03) v1(53.57,52.04) v1(53.57,50.75) v1(53.82,56.72) v1(53.82,17.55) v1(53.95,46.23) v1(54.36,38.89) v1(54.51,70.21) v1(54.48,67.56) v1(54.48,65.41) v1(54.48,63.91) v1(54.51,62.28) v1(54.48,60.45) v1(54.48,58.67) v1(54.43,53.42) v1(54.61,96.9) v1(54.61,87.76) v1(54.61,8.89) v1(54.61,5.08) v1(54.64,54.76) v1(54.74,100.36) v1(54.74,90.3) v1(54.76,85.57) v1(54.76,83.06) v1(54.74,80.85) v1(54.86,93.68) v1(54.94,95.43) v1(54.94,45.09) v1(55.09,46.79) v1(55.25,111.12) v1(55.25,104.78) v1(55.25,79.12) v1(55.27,16.15) v1(55.5,88.85) v1(55.45,42.57) v1(55.75,55.63) v1(55.88,113.67) v1(55.91,59.23) v1(55.88,52.07) v1(55.85,47.7) v1(56.26,101.98) v1(56.26,98.55) v1(56.26,91.82) v1(56.52,113.03) v1(56.52,111.76) v1(56.52,110.49) v1(56.52,109.22) v1(56.52,0.64) v1(56.54,95.48) v1(56.72,90.09) v1(56.64,56.24) v1(56.64,47.5) v1(56.64,41.3) v1(56.95,45.09) v1(57.07,85.65) v1(57.1,83.54) v1(57.07,80.72) v1(57.12,42.57) v1(57.23,64.64) v1(57.23,60.5) v1(57.15,11.43) v1(57.25,70.21) v1(57.25,67.82) v1(57.28,66.17) v1(57.25,62.81) v1(57.28,49.91) v1(57.28,33.53) v1(57.53,37.01) v1(57.71,56.21) v1(57.78,103.5) v1(57.78,46.96) v1(57.81,13.54) v1(57.94,40.03) v1(58.04,100.33) v1(58.39,79.38) v1(58.42,50.42) v1(58.45,90.14) v1(58.65,58.65) v1(58.72,56.24) v1(58.7,6.35) v1(58.8,107.57) v1(58.8,105.28) v1(58.8,74.68) v1(59.08,38.91) v1(59.11,27.97) v1(59.05,0.64) v1(59.26,46.99) v1(59.23,42.6) v1(59.41,45.06) v1(59.44,95.78) v1(59.46,93.47) v1(59.56,70.21) v1(59.59,68.71) v1(59.59,67.21) v1(59.59,65.63) v1(59.59,63.68) v1(59.59,62.43) v1(59.59,60.58) v1(59.69,6.35) v1(59.74,102.06) v1(59.87,59.49) v1(59.99,78.59) v1(60.1,11.35) v1(60.45,89.79) v1(60.45,37.85) v1(60.45,26.59) v1(60.58,41.45) v1(60.58,6.38) v1(60.66,32.74) v1(60.99,77.37) v1(60.99,75.9) v1(61.09,108.46) v1(61.09,106.55) v1(61.09,104.14) v1(61.09,97.66) v1(61.09,92.2) v1(61.09,81.66) v1(61.16,46.99) v1(61.26,34.49) v1(61.39,49.3) v1(61.47,60.27) v1(61.52,43.94) v1(61.59,0.64) v1(61.85,88.39) v1(61.9,51.66) v1(61.98,37.82) v1(62.2,24.82) v1(62.23,62.23) v1(62.38,11.07) v1(62.46,50.37) v1(62.66,41.45) v1(62.74,113.67) v1(62.86,100.33) v1(62.86,6.38) v1(63.02,34.52) v1(63.04,52.32) v1(63.04,46.99) v1(63.3,63.63) v1(63.37,49.3) v1(63.5,113.03) v1(63.5,111.76) v1(63.5,110.49) v1(63.5,109.22) v1(63.63,37.85) v1(63.73,43.99) v1(63.8,6.38) v1(63.88,94.62) v1(63.88,84.58) v1(64.03,10.92) v1(64.14,77.47) v1(64.14,0.64) v1(64.41,67.16) v1(64.41,64.74) v1(64.34,56.24) v1(64.47,52.35) v1(64.62,41.48) v1(64.69,34.49) v1(64.77,23.06) v1(64.9,46.99) v1(64.92,6.35) v1(65.15,60.99) v1(65.28,104.27) v1(65.3,62.36) v1(65.28,45.34) v1(65.41,108.59) v1(65.41,89.53) v1(65.41,73.66) v1(65.41,49.33) v1(65.38,37.82) v1(65.61,10.92) v1(65.68,53.54) v1(65.86,58.83) v1(65.91,54.99) v1(66,6.35) v1(66.04,113.67) v1(66.04,42.55) v1(66.09,32.46) v1(66.27,61.75) v1(66.42,34.52) v1(66.47,63.53) v1(66.67,0.64) v1(66.75,67.16) v1(66.75,65.2) v1(66.75,45.95) v1(66.98,10.97) v1(66.95,6.38) v1(67.21,49.33) v1(67.18,43.48) v1(67.31,85.73) v1(67.31,59) v1(67.31,26.67) v1(67.31,24.13) v1(67.49,62.41) v1(67.46,37.8) v1(67.56,56.18) v1(67.69,59.94) v1(67.72,46.99) v1(67.95,99.06) v1(67.95,95.89) v1(67.95,81.28) v1(68.02,40.11) v1(68.3,23.04) v1(68.43,50.55) v1(68.58,111.12) v1(68.58,76.2) v1(68.58,45.97) v1(68.68,58.95) v1(68.66,34.52) v1(68.73,13.03) v1(68.76,10.92) v1(68.91,62.43) v1(68.83,43.28) v1(69.22,113.67) v1(69.22,56.18) v1(69.22,6.38) v1(69.39,91.39) v1(69.42,89.74) v1(69.67,37.77) v1(69.82,63.42) v1(69.88,92.51) v1(69.85,26.67) v1(69.85,24.13) v1(69.85,0.64) v1(70.03,48.87) v1(70.03,42.06) v1(70.1,102.87) v1(70.21,6.38) v1(70.33,83.87) v1(70.36,82.32) v1(70.36,80.64) v1(70.43,88.16) v1(70.51,78.87) v1(70.48,71.75) v1(70.48,67.95) v1(70.43,45.24) v1(70.48,34.49) v1(70.54,17.22) v1(70.87,64.44) v1(71.07,23.06) v1(71.3,92.41) v1(71.3,61.49) v1(71.27,6.35) v1(71.63,90.96) v1(71.63,41.5) v1(71.65,43.99) v1(71.91,53.52) v1(71.88,37.8) v1(71.98,34.49) v1(72.16,77.22) v1(72.19,62.43) v1(72.31,65.02) v1(72.29,6.38) v1(72.39,113.67) v1(72.39,108.59) v1(72.39,98.42) v1(72.39,95.25) v1(72.39,26.67) v1(72.39,24.13) v1(72.52,58.67) v1(72.64,102.49) v1(72.72,88.82) v1(72.72,87) v1(72.69,83.95) v1(72.69,82.17) v1(72.69,79.98) v1(72.82,92.28) v1(72.75,85.6) v1(72.77,33.66) v1(72.95,17.2) v1(73.03,0.64) v1(73.13,36.8) v1(73.28,6.35) v1(73.66,104.78) v1(73.66,69.85) v1(73.71,62.74) v1(73.66,60.96) v1(73.66,48.26) v1(73.71,43.99) v1(73.69,23.04) v1(73.76,75.62) v1(73.76,41.5) v1(73.84,78.84) v1(73.84,65.02) v1(74.02,32.46) v1(74.14,90.22) v1(74.19,52.96) v1(74.45,12.4) v1(74.57,15.62) v1(74.65,36.83) v1(74.78,45.01) v1(74.93,113.67) v1(74.98,77.7) v1(74.93,24.13) v1(75.11,41.86) v1(75.08,11.89) v1(75.31,91.29) v1(75.23,62.74) v1(75.41,73.96) v1(75.36,65.02) v1(75.46,34.49) v1(75.56,97.79) v1(75.56,94.62) v1(75.59,22.17) v1(75.56,6.35) v1(75.56,0.64) v1(75.92,55.42) v1(76.02,31.27) v1(76.12,76.53) v1(76.1,52.96) v1(76.1,45.21) v1(76.05,42.7) v1(76.05,34.01) v1(76.2,111.12) v1(76.2,36.83) v1(76.2,26.67) v1(76.15,14) v1(76.53,6.38) v1(76.63,62.74) v1(76.63,45.97) v1(76.91,72.49) v1(76.83,67.95) v1(76.91,41.43) v1(77.01,65.02) v1(77.06,30.07) v1(77.32,80.26) v1(77.32,76.89) v1(77.32,20.47) v1(77.34,83.46) v1(77.37,78.69) v1(77.39,75.21) v1(77.47,113.67) v1(77.47,102.87) v1(77.47,60.96) v1(77.5,56.34) v1(77.47,48.26) v1(77.47,38.1) v1(77.47,6.38) v1(77.7,36.32) v1(77.75,46.53) v1(77.83,12.29) v1(77.9,53.29) v1(78.11,0.64) v1(78.31,71.09) v1(78.49,87.38) v1(78.54,41.12) v1(78.61,29.95) v1(78.69,35.33) v1(78.69,19.08) v1(78.69,6.35) v1(78.74,96.52) v1(78.74,26.67) v1(78.87,73.58) v1(78.99,46.48) v1(79.04,65.02) v1(79.2,58.67) v1(79.32,54.64) v1(79.38,108.59) v1(79.58,10.59) v1(79.65,83.44) v1(79.68,80.77) v1(79.65,78.59) v1(79.65,75.9) v1(79.68,69.72) v1(79.65,6.35) v1(80.01,113.67) v1(79.93,59.31) v1(80.06,50.57) v1(80.09,35.33) v1(80.14,41.15) v1(80.24,30.07) v1(80.44,46.15) v1(80.49,17.3) v1(80.57,6.38) v1(80.64,93.98) v1(80.64,71.75) v1(80.7,65.02) v1(80.67,59.54) v1(80.64,0.64) v1(80.85,60.35) v1(80.85,56.18) v1(80.9,12.09) v1(81.03,34.39) v1(81.08,42.14) v1(81.13,31.06) v1(81.15,45.44) v1(81.28,85.09) v1(81.28,26.67) v1(81.38,74.07) v1(81.51,41) v1(81.48,39.78) v1(81.48,38.05) v1(81.51,36.35) v1(81.48,35.31) v1(81.56,60.43) v1(81.81,30.35) v1(81.92,64.39) v1(81.99,46.23) v1(82.19,15.57) v1(82.25,56.21) v1(82.55,113.67) v1(82.55,111.12) v1(82.55,53.34) v1(82.8,58.67) v1(82.89,6.35) v1(82.93,90.93) v1(82.98,72.49) v1(82.98,12.07) v1(83.19,104.78) v1(83.19,96.52) v1(83.19,80.64) v1(83.21,76.68) v1(83.13,46.51) v1(83.21,29.95) v1(83.19,0.64) v1(83.31,82.55) v1(83.24,78.44) v1(83.26,74.85) v1(83.44,87.38) v1(83.44,62.03) v1(83.62,73.51) v1(83.82,36.83) v1(83.82,35.33) v1(83.82,26.67) v1(83.82,24.13) v1(83.82,13.97) v1(83.85,41.1) v1(83.85,40.01) v1(83.85,38.46) v1(83.87,6.38) v1(84.18,56.21) v1(84.33,83.54) v1(84.4,62.33) v1(84.63,35.31) v1(84.86,44.2) v1(84.86,32.28) v1(84.89,12.88) v1(84.89,6.38) v1(85.01,74.09) v1(84.96,60.81) v1(85.09,21.59) v1(85.12,11.61) v1(85.22,77.6) v1(85.19,75.69) v1(85.14,29.97) v1(85.27,46.48) v1(85.34,84.56) v1(85.42,56.54) v1(85.39,41.12) v1(85.52,33.02) v1(85.6,43.46) v1(85.72,113.67) v1(85.72,108.59) v1(85.72,100.97) v1(85.72,80.64) v1(85.65,35.33) v1(86,6.35) v1(86.11,93.85) v1(86.28,85.55) v1(86.28,82.19) v1(86.31,32.16) v1(86.28,29.92) v1(86.36,50.8) v1(86.41,44.2) v1(86.36,26.67) v1(86.36,24.13) v1(86.36,0.64) v1(86.54,59.77) v1(86.64,46.86) v1(86.82,41.15) v1(86.89,35.33) v1(86.94,6.38) v1(87.07,90.37) v1(87.07,75.46) v1(87.05,73.58) v1(87.2,29.01) v1(87.25,78.56) v1(87.35,88.75) v1(87.38,87.6) v1(87.4,82.3) v1(87.63,53.34) v1(87.63,19.05) v1(87.76,83.67) v1(87.81,41.78) v1(87.88,34.39) v1(88.09,45.06) v1(88.14,48.39) v1(88.27,97.16) v1(88.27,58.17) v1(88.42,42.77) v1(88.39,27.79) v1(88.52,73.51) v1(88.52,31.17) v1(88.65,80.19) v1(88.67,33.48) v1(88.9,113.67) v1(88.9,111.12) v1(88.9,21.59) v1(89.03,90.04) v1(89.1,46) v1(89.28,77.09) v1(89.23,6.38) v1(89.46,26.8) v1(89.53,40.01) v1(89.53,36.2) v1(89.53,0.64) v1(89.81,81.33) v1(89.76,51.97) v1(89.81,49.66) v1(89.89,97.64) v1(89.99,45.11) v1(90.22,82.98) v1(90.17,57.66) v1(90.17,24.13) v1(90.17,16.51) v1(90.22,6.35) v1(90.25,84.61) v1(90.32,42.77) v1(90.27,31.17) v1(90.35,47.32) v1(90.4,33.48) v1(90.75,82.42) v1(90.88,87.6) v1(90.86,46.28) v1(91.16,98.58) v1(91.16,90.4) v1(91.19,89.28) v1(91.19,88.39) v1(91.27,6.35) v1(91.44,113.67) v1(91.44,78.11) v1(91.44,19.05) v1(91.69,83.34) v1(91.85,31.17) v1(92.08,108.59) v1(92.1,97.69) v1(92.23,45.14) v1(92.23,42.77) v1(92.2,33.53) v1(92.2,26.52) v1(92.3,49.66) v1(92.3,47.29) v1(92.3,6.38) v1(92.48,41.83) v1(92.71,21.59) v1(92.71,13.97) v1(92.71,0.64) v1(92.86,89.56) v1(92.89,84.53) v1(93.04,98.55) v1(93.29,6.35) v1(93.34,38.1) v1(93.88,97.71) v1(93.85,61.47) v1(93.93,26.06) v1(93.98,113.67) v1(93.98,77.47) v1(93.98,50.16) v1(93.98,16.51) v1(94.08,82.45) v1(94.11,34.42) v1(94.28,99.59) v1(94.39,41.83) v1(94.56,96.09) v1(94.59,91.57) v1(94.59,89.64) v1(95.07,86) v1(95.1,83.46) v1(95.12,62.74) v1(95.15,98.68) v1(95.25,111.12) v1(95.25,104.78) v1(95.25,53.34) v1(95.25,25.4) v1(95.25,19.05) v1(95.25,11.43) v1(95.5,75.69) v1(95.58,6.4) v1(95.73,41.78) v1(95.86,26.14) v1(95.89,0.64) v1(95.96,32.87) v1(96.11,97.74) v1(96.19,96.09) v1(96.19,91.62) v1(96.16,89.61) v1(96.16,84.51) v1(96.39,86.44) v1(96.39,73.61) v1(96.52,113.67) v1(96.52,79.38) v1(96.52,55.88) v1(96.52,43.18) v1(96.52,21.59) v1(96.52,13.97) v1(96.57,6.38) v1(96.88,85.6) v1(97.16,74.3) v1(97.23,32.92) v1(97.43,88.11) v1(97.43,49.25) v1(97.49,6.4) v1(97.79,108.59) v1(97.79,89.53) v1(97.79,71.75) v1(97.79,38.1) v1(97.79,16.51) v1(97.92,34.42) v1(98.12,97.69) v1(98.09,75.26) v1(98.17,60.2) v1(98.2,41.83) v1(98.42,100.97) v1(98.45,96.09) v1(98.53,50.11) v1(98.98,73.03) v1(98.96,26.06) v1(99.06,113.67) v1(99.06,19.05) v1(99.06,11.43) v1(99.06,0.64) v1(99.14,76.3) v1(99.75,70.79) v1(100.13,73.3) v1(100.1,41.83) v1(100.2,34.42) v1(100.2,24.89) v1(100.33,53.34) v1(100.33,50.16) v1(100.33,21.59) v1(100.33,13.97) v1(100.38,80.21) v1(100.41,77.55) v1(100.56,74.42) v1(100.97,111.12) v1(101.09,60.2) v1(101.3,48.87) v1(101.3,43.08) v1(101.27,33.07) v1(101.32,30.38) v1(101.52,70.97) v1(101.52,46) v1(101.6,0.64) v1(101.73,84.84) v1(101.65,75.51) v1(101.65,27.66) v1(101.85,88.52) v1(101.93,73.3) v1(102.23,113.67) v1(102.46,48.64) v1(102.49,32.89) v1(102.54,22.48) v1(102.72,80.24) v1(102.69,76.58) v1(102.74,78.41) v1(102.87,108.59) v1(102.87,102.87) v1(102.87,92.08) v1(102.87,65.41) v1(102.87,55.88) v1(102.87,40.64) v1(102.87,36.83) v1(103.51,48.9) v1(103.58,43.31) v1(103.56,33.2) v1(103.61,30.35) v1(103.56,27.66) v1(103.66,70.94) v1(103.63,34.42) v1(103.76,45.97) v1(103.94,73.36) v1(104.14,81.92) v1(104.14,0.64) v1(104.6,26.29) v1(104.78,111.12) v1(104.78,107.95) v1(104.78,95.89) v1(104.75,50.32) v1(105,106.43) v1(105,104.14) v1(105,101.85) v1(105,99.57) v1(105,97.28) v1(105.03,41.91) v1(105.41,113.67) v1(105.41,53.34) v1(105.41,21.59) v1(105.79,34.67) v1(106.05,89.53) v1(106.12,26.29) v1(106.05,16.51) v1(106.58,70.94) v1(106.68,62.23) v1(106.65,50.32) v1(106.68,12.7) v1(106.68,3.81) v1(106.68,0.64) v1(107.01,73.3) v1(106.93,41.91) v1(107.04,106.43) v1(107.04,104.14) v1(107.04,101.85) v1(107.04,99.57) v1(107.04,97.28) v1(107.31,92.08) v1(107.54,49.17) v1(107.54,43.46) v1(107.95,113.67) v1(107.95,107.95) v1(107.95,76.84) v1(107.95,65.41) v1(107.95,36.83) v1(108.08,27.3) v1(108.2,33.12) v1(108.43,48.84) v1(108.46,43.46) v1(108.59,18.41) v1(108.59,14.61) v1(108.59,10.79) v1(109.07,106.43) v1(109.07,104.14) v1(109.05,101.85) v1(109.07,99.57) v1(109.07,97.28) v1(109.22,86.36) v1(109.22,0.64) v1(109.86,95.89) v1(109.86,81.92) v1(109.86,60.33) v1(110.24,50.42) v1(110.24,41.91) v1(110.29,26.29) v1(110.49,113.67) v1(110.49,34.92) v1(111.1,106.43) v1(111.1,104.14) v1(111.1,101.85) v1(111.1,99.57) v1(111.1,97.28) v1(111.12,62.23) v1(111.12,18.41) v1(111.12,13.34) v1(111.99,41.94) v1(112.4,107.95) v1(112.4,95.89) v1(112.4,55.88) v1(112.4,50.29) v1(112.4,38.73) v1(112.4,0.64) v1(112.6,47.47) v1(112.62,44.73) v1(112.62,34.11) v1(112.65,46.2) v1(112.73,31.83) v1(112.73,30.45) v1(112.73,29.06) v1(112.67,26.75) v1(112.8,49.81) v1(112.93,42.39) v1(113.03,113.67) v1(113.03,85.09) v1(113.03,79.38) v1(113.03,74.3) v1(113.03,71.75) v1(113.03,65.41) v1(113.03,11.43) v1(113.13,99.57) v1(113.13,97.28) v1(113.67,18.41) v1(114.1,49.78) v1(114.07,47.5) v1(114.07,44.73) v1(114.07,29.06) v1(114.17,34.19) v1(114.2,31.8) v1(114.3,106.68) v1(114.91,42.39) v1(114.94,93.98) v1(114.94,67.95) v1(115.19,53.59) v1(115.16,49.81) v1(115.14,47.47) v1(115.57,113.67) v1(115.57,0.64) v1(115.65,31.85) v1(115.67,26.67) v1(115.77,34.19) v1(115.85,44.73) v1(116.08,42.42) v1(116.08,38.35) v1(116.1,28.98) v1(116.2,81.92) v1(116.2,77.47) v1(116.2,15.88) v1(116.43,49.81) v1(116.59,31.88) v1(116.84,71.75) v1(116.84,47.47) v1(117.2,34.19) v1(117.3,42.44) v1(117.42,44.73) v1(117.48,63.5) v1(117.48,60.33) v1(117.48,55.88) v1(117.5,26.64) v1(117.48,3.81) v1(117.55,28.98) v1(117.91,49.78) v1(118.11,113.67) v1(118.11,96.52) v1(118.11,12.07) v1(118.11,0.64) v1(118.14,31.5) v1(118.39,47.47) v1(118.44,42.39) v1(118.59,45.29) v1(118.75,75.56) v1(118.92,26.64) v1(119,29.36) v1(119.08,33.78) v1(119.33,49.81) v1(119.33,42.88) v1(119.38,19.05) v1(119.38,8.2) v1(119.51,53.59) v1(119.63,31.37) v1(119.89,47.5) v1(120.02,84.45) v1(120.14,27.2) v1(120.35,45.19) v1(120.42,41.81) v1(120.65,113.67) v1(120.65,93.98) v1(120.65,87.63) v1(120.65,0.64) v1(120.8,49.81) v1(120.78,34.67) v1(120.8,32.26) v1(120.93,29.64) v1(121.29,62.23) v1(121.31,44.22) v1(121.29,38.35) v1(121.23,26.11) v1(121.29,22.86) v1(121.49,47.47) v1(121.92,55.88) v1(121.92,15.88) v1(122.05,41.81) v1(122.22,28.45) v1(122.4,45.34) v1(122.48,49.78) v1(122.56,60.33) v1(122.56,33.81) v1(122.56,31.37) v1(122.68,47.5) v1(122.83,25.98) v1(123.19,113.67) v1(123.22,42.88) v1(123.19,0.64) v1(123.57,53.72) v1(123.62,29.67) v1(123.77,34.67) v1(123.83,3.81) v1(124.21,49.78) v1(124.18,41.91) v1(124.21,32.13) v1(124.26,47.5) v1(124.31,27.23) v1(124.36,45.01) v1(124.46,93.98) v1(124.46,84.45) v1(124.46,74.3) v1(124.46,19.05) v1(125.09,88.27) v1(125.09,62.87) v1(125.09,59.69) v1(125.3,34.49) v1(125.27,29.54) v1(125.37,26.16) v1(125.48,51.08) v1(125.53,47.85) v1(125.5,31.5) v1(125.63,44.15) v1(125.7,113.69) v1(125.73,98.42) v1(125.73,55.88) v1(125.73,0.64) v1(125.81,41.83) v1(125.98,33.81) v1(126.09,6.2) v1(126.37,71.75) v1(126.39,28.4) v1(126.67,48.97) v1(126.75,38.23) v1(126.9,52.5) v1(126.85,33.81) v1(127,78.11) v1(127,22.86) v1(127.08,26.01) v1(127.43,44.12) v1(127.48,31.47) v1(127.64,15.88) v1(127.64,9.37) v1(127.74,49.99) v1(127.79,29.64) v1(127.91,41.81) v1(127.94,34.92) v1(128.17,113.67) v1(128.19,26.9) v1(128.27,62.87) v1(128.27,57.79) v1(128.27,3.81) v1(128.4,53.98) v1(128.65,45.36) v1(128.85,51.13) v1(128.91,0.64) v1(129.11,32.82) v1(129.13,36.14) v1(129.44,95.91) v1(129.44,94.39) v1(129.44,42.85) v1(129.49,27.3) v1(129.62,55.22) v1(129.9,46.63) v1(129.87,29.64) v1(130.07,52.35) v1(130.2,95.91) v1(130.2,94.39) v1(130.17,19.05) v1(130.25,37.24) v1(130.3,34.04) v1(130.43,84.07) v1(130.43,82.55) v1(130.38,26.37) v1(130.68,44.07) v1(130.81,113.67) v1(130.81,98.42) v1(130.81,60.33) v1(130.81,56.41) v1(130.96,95.91) v1(130.96,94.39) v1(131.06,40.64) v1(131.19,84.07) v1(131.19,83.31) v1(131.19,82.55) v1(131.17,53.47) v1(131.32,47.55) v1(131.37,35.05) v1(131.44,78.74) v1(131.44,69.22) v1(131.5,37.39) v1(131.44,31.75) v1(131.57,28.57) v1(131.72,95.91) v1(131.67,25.12) v1(131.8,45.19) v1(132,57.61) v1(132.08,22.86) v1(132.08,6.98) v1(132.08,0.64) v1(132.23,54.56) v1(132.49,95.15) v1(132.54,95.86) v1(132.72,84.07) v1(132.72,83.31) v1(132.72,82.55) v1(132.69,19.72) v1(132.79,27.25) v1(132.79,10.82) v1(133.1,55.37) v1(133.22,35.08) v1(133.25,47.57) v1(133.3,24.92) v1(133.35,113.67) v1(133.35,62.23) v1(133.35,37.39) v1(133.53,84.02) v1(133.48,83.31) v1(133.48,82.55) v1(133.93,57.68) v1(133.98,45.21) v1(134.04,51.44) v1(134.37,9.55) v1(134.62,107.95) v1(134.62,95.25) v1(134.62,85.09) v1(134.62,3.81) v1(134.72,27.25) v1(134.8,55.4) v1(134.77,24.89) v1(135.18,37.39) v1(135.18,35.08) v1(135.25,89.53) v1(135.25,79.38) v1(135.25,67.95) v1(135.25,31.75) v1(135.56,47.57) v1(135.64,41.28) v1(135.89,113.67) v1(135.89,98.42) v1(135.89,74.93) v1(135.89,60.33) v1(135.84,57.68) v1(135.86,10.82) v1(135.89,0.64) v1(135.99,19.72) v1(136.09,45.21) v1(136.53,15.24) v1(136.53,6.98) v1(136.6,27.25) v1(136.68,55.4) v1(136.73,24.89) v1(137.11,47.57) v1(137.11,35.08) v1(137.16,87) v1(137.16,21.59) v1(137.16,10.79) v1(137.26,37.39) v1(137.74,57.68) v1(138.18,45.21) v1(138.18,27.3) v1(138.31,19.72) v1(138.31,10.82) v1(138.43,113.67) v1(138.43,104.14) v1(138.43,74.93) v1(138.43,28.83) v1(138.43,23.24) v1(138.61,47.55) v1(138.63,55.37) v1(138.68,24.89) v1(138.89,51.44) v1(138.86,37.39) v1(138.96,35.08) v1(139.06,85.09) v1(139.06,71.75) v1(139.06,66.67) v1(139.06,62.23) v1(139.06,31.11) v1(139.06,17.78) v1(139.06,15.24) v1(139.06,12.7) v1(139.06,0.64) v1(139.32,41.4) v1(139.32,28.83) v1(139.32,23.24) v1(139.52,57.71) v1(139.83,45.21) v1(139.87,9.56) v1(140,27.25) v1(140.06,55.37) v1(140.18,24.89) v1(140.31,35.05) v1(140.34,59.33) v1(140.34,53.75) v1(140.34,49.17) v1(140.36,47.55) v1(140.34,43.59) v1(140.34,39.01) v1(140.34,33.43) v1(140.34,28.83) v1(140.34,23.24) v1(140.44,37.41) v1(140.97,113.67) v1(141.35,23.24) v1(141.41,19.72) v1(141.37,10.82) v1(141.48,59.33) v1(141.48,53.75) v1(141.48,49.17) v1(141.48,43.59) v1(141.48,39.01) v1(141.48,33.43) v1(141.48,28.83) v1(141.6,111.12) v1(141.6,108.59) v1(141.6,106.05) v1(141.6,103.5) v1(141.6,100.97) v1(141.6,98.42) v1(141.6,95.89) v1(141.6,93.34) v1(141.6,90.81) v1(141.6,88.27) v1(141.6,85.73) v1(141.6,83.19) v1(141.6,80.64) v1(141.6,78.11) v1(141.6,76.2) v1(141.6,73.66) v1(141.6,71.12) v1(141.6,68.58) v1(141.6,66.04) v1(141.6,63.5) v1(141.6,60.96) v1(141.6,57.76) v1(141.6,55.37) v1(141.6,31.17) v1(141.6,27.3) v1(141.6,24.92) v1(141.6,21.59) v1(141.6,16.51) v1(141.6,13.97) v1(141.6,8.89) v1(141.6,6.35) v1(141.6,3.81) v1(141.6,1.27) v1(141.71,45.21) v1(141.73,47.57) v1(141.73,37.41) v1(141.73,35.05) v2(43.53,41.16) v2(43.53,39.36) v2(44.43,42.06) v2(44.43,40.26) v2(45.33,42.95) v2(45.33,39.36) v2(45.33,37.56) v2(46.23,38.46) v2(47.13,37.56) v2(48.02,40.26) v2(87.22,65.3) v2(88.12,67.99) v2(89.02,68.89) v2(89.91,64.4) v2(90.81,68.89) v2(90.81,63.5) v2(91.71,66.2) v2(92.61,67.09) v2(92.61,65.3) v3(45.29,97.66) v3(45.29,97.16) v3(45.29,95.66) v3(46.76,98.65) v3(46.79,94.18) v3(48.26,98.65) v3(48.29,94.16) v3(49.78,97.66) v3(49.76,97.16) v3(49.76,95.66)
ADC_A_INN: length 34.7
  TOP w0.152: U1.5 50.65,42.34 51.97,43.66 59.79,43.66 60.88,42.57 64.52,42.57 66.5,44.55 69.11,44.55 71.09,42.57 74.29,42.57 75.51,43.79 76.78,43.79 77.11,43.46 77.11,42.75 77.57,42.29 R41.2
  TOP w0.305: R41.2 79.63,42.29 R44.2
ADC_A_INP: length 34.8
  TOP w0.152: R35.1 77.55,45.34 77.11,44.91 77.11,44.42 76.78,44.09 75.39,44.09 74.17,42.88 71.22,42.88 69.24,44.86 66.37,44.86 64.39,42.88 61.01,42.88 59.92,43.97 51.84,43.97 50.43,42.56 U1.6
  TOP w0.305: R35.1 79.63,45.34 R34.2
ADC_B_INN: length 34.7
  TOP w0.152: 51.71,41.14 51.71,41.31 52.05,41.65 52.05,41.66 52.35,41.96 54.05,41.96 59.61,36.4 71.6,36.4 73.08,34.93 75.39,32.61 76.81,32.61 77.11,32.31 77.11,31.62 77.6,31.14 R28.2
  TOP w0.305: R32.2 79.63,31.11 R28.2
ADC_B_INP: length 34.7
  TOP w0.152: R23.1 77.11,33.68 77.11,33.17 76.86,32.92 75.51,32.92 73.38,35.05 71.73,36.7 59.74,36.7 54.18,42.27 52.22,42.27 51.45,41.5 U1.3
  TOP w0.305: R23.1 79.63,34.16 R21.2
ADC_DCLKOUTN: length 48.7
  TOP w0.152: J14.56 81.72,9.56 81.72,10.25 81.71,10.26 v1(81.71,10.92) ; v1(48.74,33.2) 48.74,33.24 48.31,33.67 48.31,33.76 47.63,34.44 47.62,34.44 47.55,34.51 47.53,34.51 47.26,34.78 U1.50
  BOTTOM w0.152: v1(48.74,33.2) 48.79,33.15 48.91,33.15 48.95,33.11 48.95,32.61 63.27,18.29 65.74,18.29 66.05,18.6 66.05,19 66.21,19.15 66.82,19.15 66.97,19 66.97,18.6 67.29,18.29 68.13,18.29 68.44,18.6 68.44,19 68.59,19.15 69.2,19.15 69.36,19 69.36,18.6 69.67,18.29 73.41,18.29 80.39,11.3 80.72,11.3 81.05,10.97 81.66,10.97 v1(81.71,10.92)
ADC_DCLKOUTP: length 48.8
  TOP w0.152: v1(48.77,33.86) 48.59,33.86 48.59,33.87 47.68,34.79 47.64,34.79 47.47,34.96 U1.51 ; v1(81.25,11.46) 81.25,10.73 81.43,10.55 81.43,9.53 J14.58
  BOTTOM w0.152: v1(81.25,11.46) 80.97,11.46 80.84,11.58 80.51,11.58 80.29,11.8 80.29,12.09 80.11,12.27 79.82,12.27 73.52,18.57 69.79,18.57 69.64,18.72 69.64,19.12 69.32,19.43 68.48,19.43 68.16,19.12 68.16,18.72 68.01,18.57 67.4,18.57 67.25,18.72 67.25,19.12 66.93,19.43 66.09,19.43 65.78,19.12 65.78,18.72 65.62,18.57 63.39,18.57 49.23,32.73 49.23,33.4 48.97,33.65 48.97,33.66 v1(48.77,33.86)
ADC_FCLKOUTN: length 48.7
  TOP w0.152: J14.64 74.73,9.56 74.73,11.13 v1(74.7,11.25) ; U1.46 44.99,35.08 44.55,34.65 44.54,34.65 44.27,34.38 v1(44.27,33.71)
  BOTTOM w0.152: v1(44.27,33.71) 44.37,33.6 44.48,33.6 45.02,33.06 45.02,32.23 46.43,30.82 47.5,30.82 47.82,30.5 47.82,30.28 47.62,30.08 47.62,29.63 48.11,29.15 48.55,29.15 48.75,29.35 48.97,29.35 49.29,29.03 49.29,28.81 49.09,28.61 49.09,28.16 49.58,27.67 50.03,27.67 50.23,27.88 50.44,27.88 50.77,27.55 50.77,27.34 50.57,27.13 50.57,26.69 51.05,26.2 51.5,26.2 51.7,26.4 51.92,26.4 52.24,26.08 52.24,25.86 52.04,25.66 52.04,25.21 52.53,24.73 52.97,24.73 53.18,24.93 53.39,24.93 53.71,24.6 53.71,23.6 61.77,15.54 70.46,15.54 73.69,12.32 73.69,12.08 73.74,12.03 73.74,11.56 74.04,11.25 v1(74.7,11.25)
ADC_FCLKOUTP: length 48.7
  TOP w0.152: v1(74.22,11.76) 74.24,11.73 74.24,11.06 74.45,10.86 74.45,9.54 J14.66 ; v1(44.73,34.19) 44.73,34.29 45.22,34.78 U1.47
  BOTTOM w0.152: v1(74.22,11.76) 74.11,11.87 74.11,11.94 74.02,12.03 74.02,12.14 73.96,12.2 73.96,12.43 73.68,12.72 73.68,12.91 73.76,12.99 73.76,13.18 73.63,13.31 73.44,13.31 73.36,13.23 73.17,13.23 70.58,15.82 61.89,15.82 53.99,23.72 53.99,24.72 53.51,25.21 53.06,25.21 52.86,25.01 52.64,25.01 52.32,25.33 52.32,25.54 52.52,25.75 52.52,26.19 52.03,26.68 51.59,26.68 51.38,26.48 51.17,26.48 50.84,26.8 50.84,27.02 51.05,27.22 51.05,27.67 50.56,28.15 50.11,28.15 49.91,27.95 49.7,27.95 49.37,28.28 49.37,28.49 49.57,28.69 49.57,29.14 49.09,29.63 48.64,29.63 48.44,29.43 48.22,29.43 47.9,29.75 47.9,29.97 48.1,30.17 48.1,30.62 47.61,31.1 46.55,31.1 46.03,31.62 46.03,31.81 46.17,31.95 46.17,32.14 46.03,32.27 45.85,32.27 45.7,32.13 45.52,32.13 45.3,32.35 45.3,33.18 44.75,33.72 44.75,33.91 44.73,33.93 v1(44.73,34.19)
